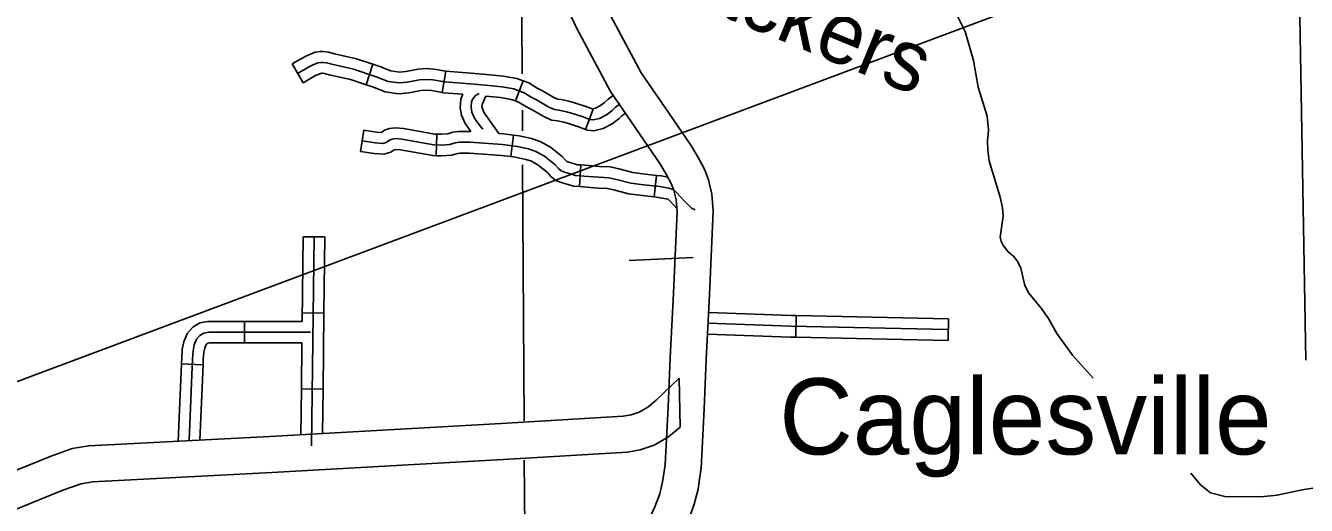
# Model space of a CAD drawing. Extents: x 1373862 to 1376999, y 1168398 to 1170455.
# Drawn here: x 1374862.3 to 1375039.9, y 1168898.2 to 1168964.7 of the extents above; entities that cross this region are included whole.
import ezdxf

# ---------------------------------------------------------------- set-up
doc = ezdxf.new("R2010")
doc.units = 0
for name, color, linetype in [('Level 10', 7, 'Continuous'), ('Level 24', 7, 'Continuous'), ('Level 32', 7, 'Continuous'), ('Level 35', 7, 'Continuous'), ('Level 4', 7, 'Continuous'), ('Level 45', 7, 'Continuous'), ('Level 5', 7, 'Continuous'), ('R_Draft', 7, 'Continuous')]:
    doc.layers.add(name, color=color, linetype=linetype)

msp = doc.modelspace()

# ---------------------------------------------------------------- linework, layer by layer
at = {"layer": 'Level 10'}
msp.add_line((1374955.72, 1168901.85), (1374955.73, 1168901.87), dxfattribs=at)
for points in [[(1374955.73, 1168901.87), (1374955.94, 1168903.35), (1374956.37, 1168911.6), (1374956.65, 1168918.43), (1374957.12, 1168927.38), (1374957.6, 1168939.05), (1374957.42, 1168941.38), (1374956.94, 1168943.33), (1374956.4, 1168944.81), (1374955.5, 1168946.53), (1374954.49, 1168948.17), (1374951.51, 1168952.53), (1374947.64, 1168958.19), (1374943.07, 1168966.74), (1374940.91, 1168971.43)], [(1374936.37, 1168969.34), (1374938.59, 1168964.52), (1374943.36, 1168955.59), (1374947.39, 1168949.71), (1374950.29, 1168945.46), (1374951.15, 1168944.06), (1374951.82, 1168942.77), (1374952.15, 1168941.88), (1374952.47, 1168940.59), (1374952.6, 1168938.96), (1374952.13, 1168927.62), (1374951.65, 1168918.66), (1374951.38, 1168911.83), (1374950.96, 1168903.84), (1374950.78, 1168902.59)], [(1374847.03, 1168897.51), (1374848.67, 1168898.35), (1374856.51, 1168901.28), (1374865.66, 1168904.97), (1374868.71, 1168906.07), (1374871.03, 1168906.44), (1374896.15, 1168907.75), (1374928.19, 1168909.55), (1374945.15, 1168910.57), (1374946.26, 1168910.76), (1374947.36, 1168911.12), (1374948.53, 1168911.81), (1374949.72, 1168912.79), (1374952.91, 1168915.86)], [(1374952.91, 1168915.86), (1374953.05, 1168909.06), (1374951.42, 1168907.71), (1374949.43, 1168906.53), (1374947.48, 1168905.9), (1374945.73, 1168905.59), (1374928.48, 1168904.56), (1374896.42, 1168902.76), (1374871.56, 1168901.46), (1374869.96, 1168901.2), (1374867.44, 1168900.3), (1374858.32, 1168896.62)], [(1374950.78, 1168902.62), (1374950.6, 1168901.45), (1374950.19, 1168899.8), (1374949.54, 1168897.99), (1374948.88, 1168896.59), (1374931.47, 1168866.72), (1374912.95, 1168834.16), (1374900.38, 1168813.55), (1374897.26, 1168808.12), (1374896.16, 1168805.15), (1374895.82, 1168803.27), (1374895.72, 1168801.48), (1374895.81, 1168799.61), (1374895.97, 1168797.8), (1374897.4, 1168789.98), (1374897.58, 1168787.68), (1374897.41, 1168782.21), (1374896.5, 1168771.93)], [(1374901.48, 1168771.48), (1374902.41, 1168781.91), (1374902.59, 1168787.8), (1374902.37, 1168790.62), (1374900.93, 1168798.47), (1374900.8, 1168799.94), (1374900.73, 1168801.46), (1374900.79, 1168802.68), (1374901, 1168803.83), (1374901.8, 1168805.99), (1374904.69, 1168811), (1374917.26, 1168831.62), (1374935.81, 1168864.23), (1374953.32, 1168894.26), (1374954.17, 1168896.09), (1374954.98, 1168898.35), (1374955.51, 1168900.45), (1374955.72, 1168901.85)]]:
    msp.add_lwpolyline(points, dxfattribs=at)
at = {"layer": 'Level 32'}
for p, q in [((1374900.74, 1168956.82), (1374899.24, 1168959.42)), ((1374909.47, 1168956.53), (1374910.43, 1168959.38)), ((1374920.02, 1168955.47), (1374920.52, 1168958.43)), ((1374930.2, 1168954.29), (1374931.25, 1168957.1)), ((1374939.89, 1168950.34), (1374940.96, 1168953.15)), ((1374908.7, 1168947.26), (1374909.15, 1168950.23)), ((1374919.21, 1168946.7), (1374919.29, 1168949.7)), ((1374929.56, 1168946.58), (1374929.92, 1168949.56)), ((1374939.05, 1168942.41), (1374939.27, 1168945.41)), ((1374949.43, 1168940.98), (1374949.76, 1168943.97)), ((1374900.76, 1168935.46), (1374903.76, 1168935.43)), ((1374900.64, 1168924.9), (1374903.64, 1168924.87)), ((1374892.64, 1168920.72), (1374892.64, 1168923.72)), ((1374886.87, 1168917.71), (1374883.87, 1168917.84)), ((1374900.51, 1168914.34), (1374903.51, 1168914.31))]:
    msp.add_line(p, q, dxfattribs=at)
for points in [[(1374899.24, 1168959.42), (1374901.14, 1168960.52), (1374902.41, 1168961.04), (1374903.12, 1168961.14), (1374903.54, 1168961.14), (1374904.26, 1168961.06), (1374905.09, 1168960.85), (1374908.15, 1168960.14), (1374910.43, 1168959.38)], [(1374899.99, 1168958.12), (1374901.81, 1168959.17), (1374902.8, 1168959.58), (1374903.22, 1168959.64), (1374903.47, 1168959.64), (1374903.99, 1168959.58), (1374904.74, 1168959.39), (1374907.74, 1168958.7), (1374910.86, 1168957.65), (1374912.52, 1168957.01), (1374914.07, 1168956.79), (1374915.2, 1168956.9), (1374916.88, 1168957.21), (1374917.85, 1168957.29), (1374918.73, 1168957.21), (1374920.36, 1168956.93), (1374923.89, 1168956.65), (1374926.02, 1168956.46), (1374928.31, 1168956.24), (1374929.99, 1168955.96), (1374931.4, 1168955.44), (1374932.45, 1168954.78), (1374933.22, 1168954.39), (1374934.82, 1168953.45), (1374935.6, 1168953.09), (1374936.26, 1168953.01), (1374937.25, 1168952.79), (1374937.97, 1168952.59), (1374939.57, 1168952.07), (1374940.51, 1168951.71), (1374940.98, 1168951.66), (1374941.83, 1168951.88), (1374942.8, 1168952.37), (1374943.55, 1168952.93), (1374944.01, 1168953.4), (1374944.7, 1168953.9)], [(1374910.43, 1168959.38), (1374911.37, 1168959.06), (1374912.9, 1168958.47), (1374914.1, 1168958.3), (1374914.99, 1168958.39), (1374916.68, 1168958.7), (1374917.85, 1168958.8), (1374918.93, 1168958.7), (1374920.52, 1168958.43)], [(1374900.74, 1168956.82), (1374902.47, 1168957.82), (1374903.2, 1168958.12), (1374903.32, 1168958.14), (1374903.39, 1168958.14), (1374903.72, 1168958.1), (1374904.38, 1168957.93), (1374907.34, 1168957.25), (1374909.47, 1168956.53)], [(1374920.52, 1168958.43), (1374920.54, 1168958.42), (1374924.02, 1168958.15), (1374926.16, 1168957.95), (1374928.5, 1168957.73), (1374930.38, 1168957.42), (1374931.25, 1168957.1)], [(1374931.25, 1168957.1), (1374932.07, 1168956.79), (1374933.19, 1168956.08), (1374933.94, 1168955.71), (1374935.52, 1168954.78), (1374936.01, 1168954.55), (1374936.51, 1168954.49), (1374937.61, 1168954.25), (1374938.4, 1168954.03), (1374940.07, 1168953.48), (1374940.96, 1168953.15)], [(1374909.47, 1168956.53), (1374910.36, 1168956.24), (1374912.14, 1168955.55), (1374914.03, 1168955.28), (1374915.4, 1168955.42), (1374917.08, 1168955.72), (1374917.84, 1168955.78), (1374918.53, 1168955.72), (1374920.02, 1168955.47)], [(1374920.02, 1168955.47), (1374920.17, 1168955.44), (1374922.91, 1168955.23)], [(1374922.91, 1168955.23), (1374922.6, 1168954.52), (1374922.51, 1168953.34), (1374922.72, 1168952.3), (1374923.21, 1168951.15), (1374924, 1168950.06)], [(1374925.14, 1168955.33), (1374924.63, 1168955.04), (1374924.27, 1168954.6), (1374924.08, 1168954.15), (1374924.03, 1168953.44), (1374924.16, 1168952.75), (1374924.52, 1168951.89), (1374925.18, 1168950.98), (1374925.67, 1168950.38)], [(1374940.87, 1168953.18), (1374940.87, 1168953.18), (1374941.3, 1168953.29), (1374942, 1168953.65), (1374942.56, 1168954.07), (1374943.03, 1168954.53), (1374943.73, 1168955.05)], [(1374926.07, 1168954.95), (1374925.56, 1168953.79), (1374925.54, 1168953.53), (1374925.6, 1168953.19), (1374925.84, 1168952.63), (1374927.91, 1168949.77)], [(1374926.07, 1168954.95), (1374928.11, 1168954.75), (1374929.61, 1168954.51), (1374930.2, 1168954.29)], [(1374930.2, 1168954.29), (1374930.73, 1168954.09), (1374931.71, 1168953.47), (1374932.51, 1168953.07), (1374934.13, 1168952.12), (1374935.18, 1168951.63), (1374936, 1168951.53), (1374936.89, 1168951.33), (1374937.54, 1168951.16), (1374939.07, 1168950.66), (1374939.89, 1168950.34)], [(1374939.89, 1168950.34), (1374940.15, 1168950.24), (1374941.08, 1168950.13), (1374942.37, 1168950.47), (1374943.59, 1168951.1), (1374944.53, 1168951.79), (1374945, 1168952.26), (1374945.42, 1168952.57)], [(1374909.15, 1168950.23), (1374910.91, 1168949.96), (1374911.61, 1168949.92), (1374912.05, 1168950.23), (1374912.75, 1168950.45), (1374913.6, 1168950.57), (1374914.67, 1168950.47), (1374919.03, 1168949.7), (1374919.29, 1168949.7)], [(1374919.29, 1168949.7), (1374919.9, 1168949.68), (1374920.82, 1168949.75), (1374921.51, 1168949.95), (1374922.31, 1168950.07), (1374923.93, 1168950.07), (1374924, 1168950.06)], [(1374927.91, 1168949.77), (1374928.55, 1168949.73), (1374929.92, 1168949.56)], [(1374908.93, 1168948.75), (1374910.75, 1168948.47), (1374911.79, 1168948.4), (1374912.26, 1168948.54), (1374912.72, 1168948.87), (1374913.08, 1168948.98), (1374913.64, 1168949.06), (1374914.46, 1168948.98), (1374918.88, 1168948.21), (1374919.93, 1168948.18), (1374921.09, 1168948.26), (1374921.83, 1168948.48), (1374922.41, 1168948.57), (1374923.88, 1168948.57), (1374928.4, 1168948.23), (1374930.45, 1168947.99), (1374932.02, 1168947.63), (1374933.01, 1168947.3), (1374934.2, 1168946.63), (1374935.64, 1168945.47), (1374936.16, 1168944.92), (1374936.55, 1168944.59), (1374936.99, 1168944.42), (1374937.62, 1168944.23), (1374938.53, 1168943.95), (1374939.69, 1168943.87), (1374941.74, 1168943.71), (1374943.12, 1168943.65), (1374944.19, 1168943.4), (1374946.18, 1168942.9), (1374947.97, 1168942.66), (1374950.21, 1168942.41), (1374951.48, 1168942.19), (1374952.06, 1168941.99), (1374952.5, 1168941.66), (1374953.69, 1168940.36), (1374954.13, 1168939.87), (1374954.6, 1168939.42), (1374955.09, 1168939.18)], [(1374929.92, 1168949.56), (1374930.7, 1168949.47), (1374932.42, 1168949.07), (1374933.62, 1168948.67), (1374935.04, 1168947.88), (1374936.65, 1168946.58), (1374937.19, 1168946.01), (1374937.32, 1168945.9), (1374937.47, 1168945.84), (1374938.06, 1168945.67), (1374938.81, 1168945.44), (1374939.27, 1168945.41)], [(1374908.7, 1168947.26), (1374910.59, 1168946.98), (1374911.95, 1168946.89), (1374912.92, 1168947.17), (1374913.39, 1168947.51), (1374913.42, 1168947.51), (1374913.67, 1168947.55), (1374914.26, 1168947.49), (1374918.73, 1168946.71), (1374919.21, 1168946.7)], [(1374919.21, 1168946.7), (1374919.96, 1168946.68), (1374921.36, 1168946.78), (1374922.15, 1168947.01), (1374922.52, 1168947.07), (1374923.82, 1168947.07), (1374928.26, 1168946.74), (1374929.56, 1168946.58)], [(1374929.56, 1168946.58), (1374930.19, 1168946.51), (1374931.61, 1168946.18), (1374932.4, 1168945.92), (1374933.36, 1168945.39), (1374934.62, 1168944.37), (1374935.12, 1168943.83), (1374935.77, 1168943.28), (1374936.51, 1168943), (1374937.19, 1168942.79), (1374938.26, 1168942.47), (1374939.05, 1168942.41)], [(1374939.27, 1168945.41), (1374939.81, 1168945.37), (1374941.83, 1168945.2), (1374943.32, 1168945.14), (1374944.54, 1168944.86), (1374946.47, 1168944.38), (1374948.16, 1168944.14), (1374949.76, 1168943.97)], [(1374949.76, 1168943.97), (1374950.42, 1168943.89), (1374951.32, 1168943.74)], [(1374939.05, 1168942.41), (1374939.58, 1168942.38), (1374941.64, 1168942.21), (1374942.92, 1168942.16), (1374943.84, 1168941.94), (1374945.89, 1168941.43), (1374947.79, 1168941.17), (1374949.43, 1168940.98)], [(1374949.43, 1168940.98), (1374950, 1168940.92), (1374951.11, 1168940.73), (1374951.35, 1168940.65), (1374951.49, 1168940.55), (1374952.61, 1168939.32)], [(1374900.76, 1168935.46), (1374900.62, 1168923.72)], [(1374902.26, 1168935.44), (1374901.92, 1168906.43)], [(1374903.76, 1168935.43), (1374903.64, 1168924.87)], [(1374954.84, 1168932.56), (1374945.96, 1168932.15)], [(1374903.64, 1168924.87), (1374903.51, 1168914.31)], [(1374883.87, 1168917.84), (1374883.91, 1168918.62), (1374884, 1168919.85), (1374884.21, 1168920.86), (1374884.66, 1168922.05), (1374885.46, 1168922.9), (1374886.42, 1168923.52), (1374887.55, 1168923.72), (1374892.64, 1168923.72)], [(1374892.64, 1168923.72), (1374900.62, 1168923.72)], [(1374884.94, 1168907.22), (1374885.4, 1168918.53), (1374885.49, 1168919.64), (1374885.65, 1168920.44), (1374885.96, 1168921.24), (1374886.43, 1168921.74), (1374886.98, 1168922.1), (1374887.68, 1168922.22), (1374901.77, 1168922.22)], [(1374886.87, 1168917.71), (1374886.9, 1168918.45), (1374886.98, 1168919.43), (1374887.1, 1168920.02), (1374887.25, 1168920.43), (1374887.39, 1168920.58), (1374887.54, 1168920.67), (1374887.81, 1168920.72), (1374892.64, 1168920.72)], [(1374892.64, 1168920.72), (1374900.59, 1168920.72)], [(1374900.59, 1168920.72), (1374900.51, 1168914.34)], [(1374883.43, 1168907.09), (1374883.87, 1168917.84)], [(1374886.44, 1168907.24), (1374886.87, 1168917.71)], [(1374900.51, 1168914.34), (1374900.44, 1168907.99)], [(1374903.51, 1168914.31), (1374903.44, 1168908.16)]]:
    msp.add_lwpolyline(points, dxfattribs=at)
at = {"layer": 'Level 35'}
for points in [[(1374991.44, 1168966.13), (1374992.53, 1168963.94), (1374993.7, 1168959.91), (1374994.37, 1168956.2), (1374995.59, 1168952.17), (1374995.78, 1168950.22), (1374995.66, 1168948.78), (1374995.68, 1168947.46), (1374995.89, 1168946), (1374997.38, 1168940.95), (1374997.73, 1168939.45), (1374997.82, 1168938.33), (1374997.41, 1168935.4), (1374997.54, 1168934.8), (1374997.87, 1168934.18), (1374998.52, 1168933.35), (1374999.31, 1168932.72), (1374999.86, 1168931.97), (1375000.29, 1168931.11), (1375000.83, 1168928.68), (1375001.36, 1168927.62), (1375003.11, 1168925.56), (1375004.1, 1168924.12), (1375005.25, 1168922.03), (1375007.43, 1168919.04), (1375010.29, 1168915.82)], [(1375023.85, 1168902.66), (1375025.16, 1168901.03), (1375026.57, 1168899.93), (1375028.56, 1168899.4), (1375033.52, 1168899.39), (1375035.81, 1168899.59), (1375039.3, 1168900.36), (1375040.76, 1168900.56)]]:
    msp.add_lwpolyline(points, dxfattribs=at)
at = {"layer": 'Level 4'}
for points in [[(1374931, 1168980.63), (1374931.12, 1168958.04)], [(1374931.15, 1168953.01), (1374931.17, 1168950.14)], [(1374931.19, 1168945.44), (1374931.39, 1168909.92)], [(1374931.42, 1168904.44), (1374931.48, 1168895.02), (1374931.49, 1168892.74), (1374931.49, 1168866.89)]]:
    msp.add_lwpolyline(points, dxfattribs=at)
at = {"layer": 'Level 45'}
for p, q in [((1374969.12, 1168924.52), (1374969.05, 1168921.53)), ((1374990.23, 1168924.08), (1374990.17, 1168921.08))]:
    msp.add_line(p, q, dxfattribs=at)
for points in [[(1374969.12, 1168924.52), (1374968.4, 1168924.54), (1374957, 1168924.96)], [(1374990.2, 1168922.58), (1374968.36, 1168923.04), (1374956.85, 1168923.46)], [(1374979.67, 1168924.3), (1374969.12, 1168924.52)], [(1374990.23, 1168924.08), (1374979.67, 1168924.3)], [(1374969.05, 1168921.53), (1374968.32, 1168921.54), (1374956.84, 1168921.96)], [(1374979.61, 1168921.3), (1374969.05, 1168921.53)], [(1374990.17, 1168921.08), (1374979.61, 1168921.3)]]:
    msp.add_lwpolyline(points, dxfattribs=at)
at = {"layer": 'Level 5'}
msp.add_lwpolyline([(1375038.34, 1169000.46), (1375039.8, 1168918.35)], dxfattribs=at)
at = {"layer": 'R_Draft'}
msp.add_line((1375430.86, 1169128.62), (1374608.59, 1168820.86), dxfattribs=at)

# ---------------------------------------------------------------- texts
at = {"layer": 'Level 24'}
msp.add_text('Caglesville', height=10.56, dxfattribs=at).set_placement((1374966.77, 1168905.26))
at = {"layer": 'Level 35'}
msp.add_text('Hackers', height=8.448, rotation=337.6494, dxfattribs=at).set_placement((1374947.39, 1168970.74))

doc.saveas('drawing.dxf')
